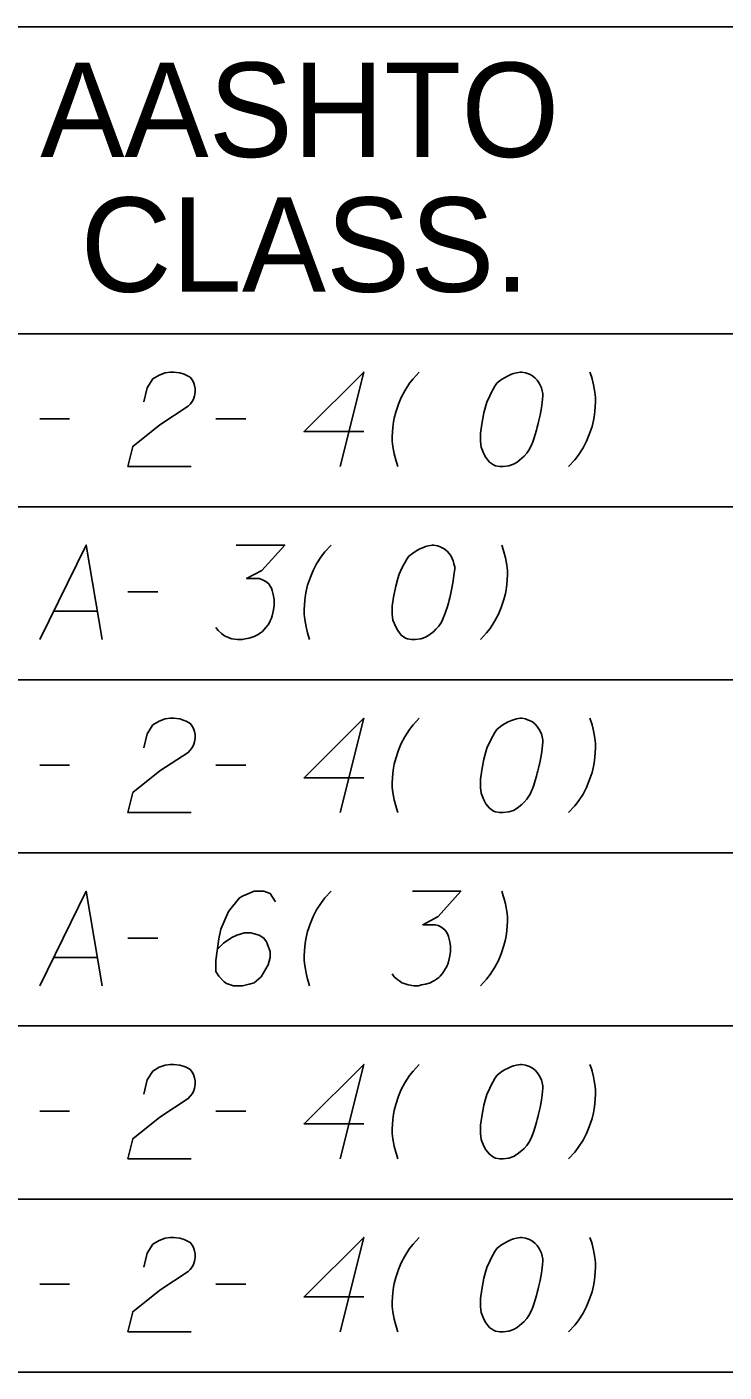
# Model space of a CAD drawing. Extents: x 2074207 to 2076812, y 516372 to 523312.
# Drawn here: x 2076453.5 to 2076488.9, y 516443.1 to 516511.5 of the extents above; entities that cross this region are included whole.
import ezdxf

# ---------------------------------------------------------------- set-up
doc = ezdxf.new("R2010")
doc.units = 0
for name, color, linetype in [('Prop DirtTable_ Soil Test Results - Outline (Major)', 7, 'Continuous'), ('Prop DirtTable_ Soil Test Results - Outline (Minor)', 7, 'Continuous'), ('Prop DirtTable_ Soil Test Results - Tx (Header - Small)', 7, 'Continuous'), ('Prop DirtTable_ Soil Test Results - Tx (Sample Data)', 7, 'Continuous')]:
    doc.layers.add(name, color=color, linetype=linetype)

msp = doc.modelspace()

# ---------------------------------------------------------------- linework, layer by layer
at = {"layer": 'Prop DirtTable_ Soil Test Results - Outline (Major)'}
for p, q in [((2076260.609, 516495.938), (2076811.903, 516495.938)), ((2076260.609, 516495.938), (2076811.903, 516495.938)), ((2076260.609, 516443.138), (2076811.903, 516443.138))]:
    msp.add_line(p, q, dxfattribs=at)
at = {"layer": 'Prop DirtTable_ Soil Test Results - Outline (Minor)'}
for p, q in [((2076260.609, 516511.538), (2076811.903, 516511.538)), ((2076260.609, 516487.138), (2076811.903, 516487.138)), ((2076260.609, 516487.138), (2076811.903, 516487.138)), ((2076260.609, 516478.338), (2076811.903, 516478.338)), ((2076260.609, 516478.338), (2076811.903, 516478.338)), ((2076260.609, 516469.538), (2076811.903, 516469.538)), ((2076260.609, 516469.538), (2076811.903, 516469.538)), ((2076260.609, 516460.738), (2076811.903, 516460.738)), ((2076260.609, 516460.738), (2076811.903, 516460.738)), ((2076260.609, 516451.938), (2076811.903, 516451.938)), ((2076260.609, 516451.938), (2076811.903, 516451.938)), ((2076260.609, 516443.138), (2076811.903, 516443.138))]:
    msp.add_line(p, q, dxfattribs=at)
at = {"layer": 'Prop DirtTable_ Soil Test Results - Tx (Sample Data)'}
for points in [[(2076459.447, 516492.474), (2076459.623, 516493.192), (2076459.906, 516493.646), (2076460.223, 516493.835), (2076460.54, 516493.948), (2076460.787, 516493.986), (2076460.964, 516493.986), (2076461.281, 516493.948), (2076461.493, 516493.873), (2076461.599, 516493.835), (2076461.81, 516493.722), (2076461.916, 516493.57), (2076461.987, 516493.419), (2076462.022, 516493.306), (2076462.057, 516493.155), (2076462.057, 516492.966), (2076462.022, 516492.777), (2076461.987, 516492.663), (2076461.916, 516492.512), (2076461.81, 516492.361), (2076461.705, 516492.248), (2076460.258, 516491.303), (2076458.883, 516490.207), (2076458.636, 516489.186), (2076461.846, 516489.186)], [(2076470.629, 516490.963), (2076467.596, 516490.963), (2076470.629, 516493.986), (2076469.43, 516489.186)], [(2076473.451, 516493.986), (2076473.134, 516493.646), (2076472.958, 516493.419), (2076472.711, 516493.041), (2076472.534, 516492.701), (2076472.393, 516492.361), (2076472.252, 516491.945), (2076472.181, 516491.643), (2076472.146, 516491.454), (2076472.111, 516491.189), (2076472.076, 516490.698), (2076472.076, 516490.471), (2076472.111, 516490.207), (2076472.146, 516490.018), (2076472.181, 516489.829), (2076472.252, 516489.526), (2076472.287, 516489.413), (2076472.358, 516489.186)], [(2076478.672, 516493.986), (2076478.602, 516493.986), (2076478.39, 516493.948), (2076478.249, 516493.911), (2076478.143, 516493.873), (2076477.967, 516493.797), (2076477.755, 516493.684), (2076477.579, 516493.57), (2076477.402, 516493.419), (2076477.296, 516493.268), (2076477.191, 516493.079), (2076477.085, 516492.89), (2076476.979, 516492.663), (2076476.908, 516492.512), (2076476.838, 516492.285), (2076476.732, 516491.907), (2076476.626, 516491.341), (2076476.556, 516490.887), (2076476.556, 516490.471), (2076476.591, 516490.169), (2076476.732, 516489.829), (2076476.838, 516489.64), (2076477.014, 516489.413), (2076477.226, 516489.262), (2076477.332, 516489.224), (2076477.543, 516489.186), (2076477.72, 516489.186), (2076478.002, 516489.224), (2076478.249, 516489.3), (2076478.425, 516489.413), (2076478.672, 516489.602), (2076478.778, 516489.715), (2076478.919, 516489.866), (2076479.025, 516490.018), (2076479.095, 516490.131), (2076479.166, 516490.32), (2076479.201, 516490.396), (2076479.272, 516490.585), (2076479.342, 516490.811), (2076479.413, 516491.038), (2076479.448, 516491.189), (2076479.483, 516491.303), (2076479.519, 516491.454), (2076479.589, 516491.794), (2076479.625, 516491.983), (2076479.66, 516492.172), (2076479.695, 516492.437), (2076479.73, 516492.777), (2076479.73, 516492.89), (2076479.695, 516493.041), (2076479.66, 516493.192), (2076479.554, 516493.419), (2076479.448, 516493.57), (2076479.342, 516493.684), (2076479.201, 516493.797), (2076479.06, 516493.873), (2076478.954, 516493.911), (2076478.849, 516493.948), (2076478.672, 516493.986)], [(2076481.036, 516489.186), (2076481.353, 516489.526), (2076481.529, 516489.753), (2076481.776, 516490.131), (2076481.953, 516490.471), (2076482.094, 516490.811), (2076482.235, 516491.227), (2076482.306, 516491.529), (2076482.341, 516491.718), (2076482.376, 516491.983), (2076482.411, 516492.474), (2076482.411, 516492.701), (2076482.376, 516492.966), (2076482.341, 516493.155), (2076482.306, 516493.344), (2076482.235, 516493.646), (2076482.2, 516493.759), (2076482.129, 516493.986)], [(2076454.156, 516491.605), (2076455.672, 516491.605)], [(2076463.116, 516491.605), (2076464.632, 516491.605)], [(2076454.156, 516480.386), (2076456.519, 516485.186), (2076457.33, 516480.386)], [(2076464.139, 516485.186), (2076466.608, 516485.186), (2076465.444, 516483.901), (2076464.668, 516483.485), (2076465.303, 516483.485), (2076465.444, 516483.448), (2076465.514, 516483.41), (2076465.585, 516483.372), (2076465.655, 516483.334), (2076465.797, 516483.221), (2076465.867, 516483.107), (2076465.938, 516482.994), (2076465.973, 516482.881), (2076466.043, 516482.616), (2076466.079, 516482.389), (2076466.079, 516482.276), (2076466.079, 516482.125), (2076466.043, 516481.898), (2076466.008, 516481.747), (2076465.973, 516481.596), (2076465.938, 516481.482), (2076465.902, 516481.407), (2076465.867, 516481.331), (2076465.832, 516481.255), (2076465.761, 516481.142), (2076465.655, 516480.991), (2076465.55, 516480.878), (2076465.479, 516480.802), (2076465.373, 516480.726), (2076465.267, 516480.651), (2076465.126, 516480.575), (2076465.056, 516480.537), (2076464.809, 516480.462), (2076464.597, 516480.424), (2076464.456, 516480.386), (2076464.209, 516480.386), (2076463.927, 516480.424), (2076463.821, 516480.462), (2076463.715, 516480.5), (2076463.609, 516480.537), (2076463.504, 516480.613), (2076463.398, 516480.689), (2076463.221, 516480.84), (2076463.116, 516480.991)], [(2076468.971, 516485.186), (2076468.654, 516484.846), (2076468.478, 516484.619), (2076468.231, 516484.241), (2076468.054, 516483.901), (2076467.913, 516483.561), (2076467.772, 516483.145), (2076467.701, 516482.843), (2076467.666, 516482.654), (2076467.631, 516482.389), (2076467.596, 516481.898), (2076467.596, 516481.671), (2076467.631, 516481.407), (2076467.666, 516481.218), (2076467.701, 516481.029), (2076467.772, 516480.726), (2076467.807, 516480.613), (2076467.878, 516480.386)], [(2076474.192, 516485.186), (2076474.122, 516485.186), (2076473.91, 516485.148), (2076473.769, 516485.111), (2076473.663, 516485.073), (2076473.487, 516484.997), (2076473.275, 516484.884), (2076473.099, 516484.77), (2076472.922, 516484.619), (2076472.816, 516484.468), (2076472.711, 516484.279), (2076472.605, 516484.09), (2076472.499, 516483.863), (2076472.428, 516483.712), (2076472.358, 516483.485), (2076472.252, 516483.107), (2076472.146, 516482.541), (2076472.076, 516482.087), (2076472.076, 516481.671), (2076472.111, 516481.369), (2076472.252, 516481.029), (2076472.358, 516480.84), (2076472.534, 516480.613), (2076472.746, 516480.462), (2076472.852, 516480.424), (2076473.063, 516480.386), (2076473.24, 516480.386), (2076473.522, 516480.424), (2076473.769, 516480.5), (2076473.945, 516480.613), (2076474.192, 516480.802), (2076474.298, 516480.915), (2076474.439, 516481.066), (2076474.545, 516481.218), (2076474.615, 516481.331), (2076474.686, 516481.52), (2076474.721, 516481.596), (2076474.792, 516481.785), (2076474.862, 516482.011), (2076474.933, 516482.238), (2076474.968, 516482.389), (2076475.003, 516482.503), (2076475.039, 516482.654), (2076475.109, 516482.994), (2076475.145, 516483.183), (2076475.18, 516483.372), (2076475.215, 516483.637), (2076475.25, 516483.977), (2076475.25, 516484.09), (2076475.215, 516484.241), (2076475.18, 516484.392), (2076475.074, 516484.619), (2076474.968, 516484.77), (2076474.862, 516484.884), (2076474.721, 516484.997), (2076474.58, 516485.073), (2076474.474, 516485.111), (2076474.369, 516485.148), (2076474.192, 516485.186)], [(2076476.556, 516480.386), (2076476.873, 516480.726), (2076477.049, 516480.953), (2076477.296, 516481.331), (2076477.473, 516481.671), (2076477.614, 516482.011), (2076477.755, 516482.427), (2076477.826, 516482.729), (2076477.861, 516482.918), (2076477.896, 516483.183), (2076477.931, 516483.674), (2076477.931, 516483.901), (2076477.896, 516484.166), (2076477.861, 516484.355), (2076477.826, 516484.544), (2076477.755, 516484.846), (2076477.72, 516484.959), (2076477.649, 516485.186)], [(2076458.636, 516482.805), (2076460.152, 516482.805)], [(2076454.861, 516481.822), (2076457.083, 516481.822)], [(2076459.447, 516474.874), (2076459.623, 516475.592), (2076459.906, 516476.046), (2076460.223, 516476.235), (2076460.54, 516476.348), (2076460.787, 516476.386), (2076460.964, 516476.386), (2076461.281, 516476.348), (2076461.493, 516476.273), (2076461.599, 516476.235), (2076461.81, 516476.122), (2076461.916, 516475.97), (2076461.987, 516475.819), (2076462.022, 516475.706), (2076462.057, 516475.555), (2076462.057, 516475.366), (2076462.022, 516475.177), (2076461.987, 516475.063), (2076461.916, 516474.912), (2076461.81, 516474.761), (2076461.705, 516474.648), (2076460.258, 516473.703), (2076458.883, 516472.607), (2076458.636, 516471.586), (2076461.846, 516471.586)], [(2076470.629, 516473.363), (2076467.596, 516473.363), (2076470.629, 516476.386), (2076469.43, 516471.586)], [(2076473.451, 516476.386), (2076473.134, 516476.046), (2076472.958, 516475.819), (2076472.711, 516475.441), (2076472.534, 516475.101), (2076472.393, 516474.761), (2076472.252, 516474.345), (2076472.181, 516474.043), (2076472.146, 516473.854), (2076472.111, 516473.589), (2076472.076, 516473.098), (2076472.076, 516472.871), (2076472.111, 516472.607), (2076472.146, 516472.418), (2076472.181, 516472.229), (2076472.252, 516471.926), (2076472.287, 516471.813), (2076472.358, 516471.586)], [(2076478.672, 516476.386), (2076478.602, 516476.386), (2076478.39, 516476.348), (2076478.249, 516476.311), (2076478.143, 516476.273), (2076477.967, 516476.197), (2076477.755, 516476.084), (2076477.579, 516475.97), (2076477.402, 516475.819), (2076477.296, 516475.668), (2076477.191, 516475.479), (2076477.085, 516475.29), (2076476.979, 516475.063), (2076476.908, 516474.912), (2076476.838, 516474.685), (2076476.732, 516474.307), (2076476.626, 516473.741), (2076476.556, 516473.287), (2076476.556, 516472.871), (2076476.591, 516472.569), (2076476.732, 516472.229), (2076476.838, 516472.04), (2076477.014, 516471.813), (2076477.226, 516471.662), (2076477.332, 516471.624), (2076477.543, 516471.586), (2076477.72, 516471.586), (2076478.002, 516471.624), (2076478.249, 516471.7), (2076478.425, 516471.813), (2076478.672, 516472.002), (2076478.778, 516472.115), (2076478.919, 516472.266), (2076479.025, 516472.418), (2076479.095, 516472.531), (2076479.166, 516472.72), (2076479.201, 516472.796), (2076479.272, 516472.985), (2076479.342, 516473.211), (2076479.413, 516473.438), (2076479.448, 516473.589), (2076479.483, 516473.703), (2076479.519, 516473.854), (2076479.589, 516474.194), (2076479.625, 516474.383), (2076479.66, 516474.572), (2076479.695, 516474.837), (2076479.73, 516475.177), (2076479.73, 516475.29), (2076479.695, 516475.441), (2076479.66, 516475.592), (2076479.554, 516475.819), (2076479.448, 516475.97), (2076479.342, 516476.084), (2076479.201, 516476.197), (2076479.06, 516476.273), (2076478.954, 516476.311), (2076478.849, 516476.348), (2076478.672, 516476.386)], [(2076481.036, 516471.586), (2076481.353, 516471.926), (2076481.529, 516472.153), (2076481.776, 516472.531), (2076481.953, 516472.871), (2076482.094, 516473.211), (2076482.235, 516473.627), (2076482.306, 516473.929), (2076482.341, 516474.118), (2076482.376, 516474.383), (2076482.411, 516474.874), (2076482.411, 516475.101), (2076482.376, 516475.366), (2076482.341, 516475.555), (2076482.306, 516475.744), (2076482.235, 516476.046), (2076482.2, 516476.159), (2076482.129, 516476.386)], [(2076454.156, 516474.005), (2076455.672, 516474.005)], [(2076463.116, 516474.005), (2076464.632, 516474.005)], [(2076454.156, 516462.786), (2076456.519, 516467.586), (2076457.33, 516462.786)], [(2076466.149, 516467.057), (2076465.867, 516467.473), (2076465.55, 516467.586), (2076465.056, 516467.586), (2076464.703, 516467.435), (2076464.491, 516467.359), (2076464.315, 516467.246), (2076463.751, 516466.566), (2076463.363, 516465.659), (2076463.257, 516465.167), (2076463.116, 516464.071), (2076463.116, 516463.504), (2076463.257, 516463.278), (2076463.539, 516462.975), (2076463.645, 516462.9), (2076463.998, 516462.786), (2076464.456, 516462.786), (2076464.809, 516462.862), (2076465.056, 516462.937), (2076465.409, 516463.24), (2076465.761, 516463.844), (2076465.867, 516464.222), (2076465.867, 516464.525), (2076465.691, 516465.016), (2076465.55, 516465.205), (2076465.303, 516465.356), (2076464.879, 516465.47), (2076464.562, 516465.47), (2076464.174, 516465.356), (2076463.927, 516465.243), (2076463.504, 516464.941), (2076463.292, 516464.752), (2076463.186, 516464.638)], [(2076468.971, 516467.586), (2076468.654, 516467.246), (2076468.478, 516467.019), (2076468.231, 516466.641), (2076468.054, 516466.301), (2076467.913, 516465.961), (2076467.772, 516465.545), (2076467.701, 516465.243), (2076467.666, 516465.054), (2076467.631, 516464.789), (2076467.596, 516464.298), (2076467.596, 516464.071), (2076467.631, 516463.807), (2076467.666, 516463.618), (2076467.701, 516463.429), (2076467.772, 516463.126), (2076467.807, 516463.013), (2076467.878, 516462.786)], [(2076473.099, 516467.586), (2076475.568, 516467.586), (2076474.404, 516466.301), (2076473.628, 516465.885), (2076474.263, 516465.885), (2076474.404, 516465.848), (2076474.474, 516465.81), (2076474.545, 516465.772), (2076474.615, 516465.734), (2076474.757, 516465.621), (2076474.827, 516465.507), (2076474.898, 516465.394), (2076474.933, 516465.281), (2076475.003, 516465.016), (2076475.039, 516464.789), (2076475.039, 516464.676), (2076475.039, 516464.525), (2076475.003, 516464.298), (2076474.968, 516464.147), (2076474.933, 516463.996), (2076474.898, 516463.882), (2076474.862, 516463.807), (2076474.827, 516463.731), (2076474.792, 516463.655), (2076474.721, 516463.542), (2076474.615, 516463.391), (2076474.51, 516463.278), (2076474.439, 516463.202), (2076474.333, 516463.126), (2076474.227, 516463.051), (2076474.086, 516462.975), (2076474.016, 516462.937), (2076473.769, 516462.862), (2076473.557, 516462.824), (2076473.416, 516462.786), (2076473.169, 516462.786), (2076472.887, 516462.824), (2076472.781, 516462.862), (2076472.675, 516462.9), (2076472.569, 516462.937), (2076472.464, 516463.013), (2076472.358, 516463.089), (2076472.181, 516463.24), (2076472.076, 516463.391)], [(2076476.556, 516462.786), (2076476.873, 516463.126), (2076477.049, 516463.353), (2076477.296, 516463.731), (2076477.473, 516464.071), (2076477.614, 516464.411), (2076477.755, 516464.827), (2076477.826, 516465.129), (2076477.861, 516465.318), (2076477.896, 516465.583), (2076477.931, 516466.074), (2076477.931, 516466.301), (2076477.896, 516466.566), (2076477.861, 516466.755), (2076477.826, 516466.944), (2076477.755, 516467.246), (2076477.72, 516467.359), (2076477.649, 516467.586)], [(2076458.636, 516465.205), (2076460.152, 516465.205)], [(2076454.861, 516464.222), (2076457.083, 516464.222)], [(2076459.447, 516457.274), (2076459.623, 516457.992), (2076459.906, 516458.446), (2076460.223, 516458.635), (2076460.54, 516458.748), (2076460.787, 516458.786), (2076460.964, 516458.786), (2076461.281, 516458.748), (2076461.493, 516458.673), (2076461.599, 516458.635), (2076461.81, 516458.522), (2076461.916, 516458.37), (2076461.987, 516458.219), (2076462.022, 516458.106), (2076462.057, 516457.955), (2076462.057, 516457.766), (2076462.022, 516457.577), (2076461.987, 516457.463), (2076461.916, 516457.312), (2076461.81, 516457.161), (2076461.705, 516457.048), (2076460.258, 516456.103), (2076458.883, 516455.007), (2076458.636, 516453.986), (2076461.846, 516453.986)], [(2076470.629, 516455.763), (2076467.596, 516455.763), (2076470.629, 516458.786), (2076469.43, 516453.986)], [(2076473.451, 516458.786), (2076473.134, 516458.446), (2076472.958, 516458.219), (2076472.711, 516457.841), (2076472.534, 516457.501), (2076472.393, 516457.161), (2076472.252, 516456.745), (2076472.181, 516456.443), (2076472.146, 516456.254), (2076472.111, 516455.989), (2076472.076, 516455.498), (2076472.076, 516455.271), (2076472.111, 516455.007), (2076472.146, 516454.818), (2076472.181, 516454.629), (2076472.252, 516454.326), (2076472.287, 516454.213), (2076472.358, 516453.986)], [(2076478.672, 516458.786), (2076478.602, 516458.786), (2076478.39, 516458.748), (2076478.249, 516458.711), (2076478.143, 516458.673), (2076477.967, 516458.597), (2076477.755, 516458.484), (2076477.579, 516458.37), (2076477.402, 516458.219), (2076477.296, 516458.068), (2076477.191, 516457.879), (2076477.085, 516457.69), (2076476.979, 516457.463), (2076476.908, 516457.312), (2076476.838, 516457.085), (2076476.732, 516456.707), (2076476.626, 516456.141), (2076476.556, 516455.687), (2076476.556, 516455.271), (2076476.591, 516454.969), (2076476.732, 516454.629), (2076476.838, 516454.44), (2076477.014, 516454.213), (2076477.226, 516454.062), (2076477.332, 516454.024), (2076477.543, 516453.986), (2076477.72, 516453.986), (2076478.002, 516454.024), (2076478.249, 516454.1), (2076478.425, 516454.213), (2076478.672, 516454.402), (2076478.778, 516454.515), (2076478.919, 516454.666), (2076479.025, 516454.818), (2076479.095, 516454.931), (2076479.166, 516455.12), (2076479.201, 516455.196), (2076479.272, 516455.385), (2076479.342, 516455.611), (2076479.413, 516455.838), (2076479.448, 516455.989), (2076479.483, 516456.103), (2076479.519, 516456.254), (2076479.589, 516456.594), (2076479.625, 516456.783), (2076479.66, 516456.972), (2076479.695, 516457.237), (2076479.73, 516457.577), (2076479.73, 516457.69), (2076479.695, 516457.841), (2076479.66, 516457.992), (2076479.554, 516458.219), (2076479.448, 516458.37), (2076479.342, 516458.484), (2076479.201, 516458.597), (2076479.06, 516458.673), (2076478.954, 516458.711), (2076478.849, 516458.748), (2076478.672, 516458.786)], [(2076481.036, 516453.986), (2076481.353, 516454.326), (2076481.529, 516454.553), (2076481.776, 516454.931), (2076481.953, 516455.271), (2076482.094, 516455.611), (2076482.235, 516456.027), (2076482.306, 516456.329), (2076482.341, 516456.518), (2076482.376, 516456.783), (2076482.411, 516457.274), (2076482.411, 516457.501), (2076482.376, 516457.766), (2076482.341, 516457.955), (2076482.306, 516458.144), (2076482.235, 516458.446), (2076482.2, 516458.559), (2076482.129, 516458.786)], [(2076454.156, 516456.405), (2076455.672, 516456.405)], [(2076463.116, 516456.405), (2076464.632, 516456.405)], [(2076459.447, 516448.474), (2076459.623, 516449.192), (2076459.906, 516449.646), (2076460.223, 516449.835), (2076460.54, 516449.948), (2076460.787, 516449.986), (2076460.964, 516449.986), (2076461.281, 516449.948), (2076461.493, 516449.873), (2076461.599, 516449.835), (2076461.81, 516449.722), (2076461.916, 516449.57), (2076461.987, 516449.419), (2076462.022, 516449.306), (2076462.057, 516449.155), (2076462.057, 516448.966), (2076462.022, 516448.777), (2076461.987, 516448.663), (2076461.916, 516448.512), (2076461.81, 516448.361), (2076461.705, 516448.248), (2076460.258, 516447.303), (2076458.883, 516446.207), (2076458.636, 516445.186), (2076461.846, 516445.186)], [(2076470.629, 516446.963), (2076467.596, 516446.963), (2076470.629, 516449.986), (2076469.43, 516445.186)], [(2076473.451, 516449.986), (2076473.134, 516449.646), (2076472.958, 516449.419), (2076472.711, 516449.041), (2076472.534, 516448.701), (2076472.393, 516448.361), (2076472.252, 516447.945), (2076472.181, 516447.643), (2076472.146, 516447.454), (2076472.111, 516447.189), (2076472.076, 516446.698), (2076472.076, 516446.471), (2076472.111, 516446.207), (2076472.146, 516446.018), (2076472.181, 516445.829), (2076472.252, 516445.526), (2076472.287, 516445.413), (2076472.358, 516445.186)], [(2076478.672, 516449.986), (2076478.602, 516449.986), (2076478.39, 516449.948), (2076478.249, 516449.911), (2076478.143, 516449.873), (2076477.967, 516449.797), (2076477.755, 516449.684), (2076477.579, 516449.57), (2076477.402, 516449.419), (2076477.296, 516449.268), (2076477.191, 516449.079), (2076477.085, 516448.89), (2076476.979, 516448.663), (2076476.908, 516448.512), (2076476.838, 516448.285), (2076476.732, 516447.907), (2076476.626, 516447.341), (2076476.556, 516446.887), (2076476.556, 516446.471), (2076476.591, 516446.169), (2076476.732, 516445.829), (2076476.838, 516445.64), (2076477.014, 516445.413), (2076477.226, 516445.262), (2076477.332, 516445.224), (2076477.543, 516445.186), (2076477.72, 516445.186), (2076478.002, 516445.224), (2076478.249, 516445.3), (2076478.425, 516445.413), (2076478.672, 516445.602), (2076478.778, 516445.715), (2076478.919, 516445.866), (2076479.025, 516446.018), (2076479.095, 516446.131), (2076479.166, 516446.32), (2076479.201, 516446.396), (2076479.272, 516446.585), (2076479.342, 516446.811), (2076479.413, 516447.038), (2076479.448, 516447.189), (2076479.483, 516447.303), (2076479.519, 516447.454), (2076479.589, 516447.794), (2076479.625, 516447.983), (2076479.66, 516448.172), (2076479.695, 516448.437), (2076479.73, 516448.777), (2076479.73, 516448.89), (2076479.695, 516449.041), (2076479.66, 516449.192), (2076479.554, 516449.419), (2076479.448, 516449.57), (2076479.342, 516449.684), (2076479.201, 516449.797), (2076479.06, 516449.873), (2076478.954, 516449.911), (2076478.849, 516449.948), (2076478.672, 516449.986)], [(2076481.036, 516445.186), (2076481.353, 516445.526), (2076481.529, 516445.753), (2076481.776, 516446.131), (2076481.953, 516446.471), (2076482.094, 516446.811), (2076482.235, 516447.227), (2076482.306, 516447.529), (2076482.341, 516447.718), (2076482.376, 516447.983), (2076482.411, 516448.474), (2076482.411, 516448.701), (2076482.376, 516448.966), (2076482.341, 516449.155), (2076482.306, 516449.344), (2076482.235, 516449.646), (2076482.2, 516449.759), (2076482.129, 516449.986)], [(2076454.156, 516447.605), (2076455.672, 516447.605)], [(2076463.116, 516447.605), (2076464.632, 516447.605)]]:
    msp.add_lwpolyline(points, dxfattribs=at)

# ---------------------------------------------------------------- texts
at = {"layer": 'Prop DirtTable_ Soil Test Results - Tx (Header - Small)'}
for s, p in [('AASHTO', (2076454.182, 516504.924)), ('CLASS.', (2076456.225, 516498.067))]:
    msp.add_text(s, height=4.8, dxfattribs=at).set_placement(p)

doc.saveas('drawing.dxf')
